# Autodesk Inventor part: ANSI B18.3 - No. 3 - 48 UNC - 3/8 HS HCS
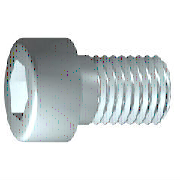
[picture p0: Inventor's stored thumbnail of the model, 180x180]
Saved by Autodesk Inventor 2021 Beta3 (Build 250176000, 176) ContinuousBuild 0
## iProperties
IsCustomPart: 0
Created: 2012-02
Part Number: ANSI B18.3 - No. 3 - 48 UNC - 3/8 HS HCS
Material: Generic
Description: Hexagon Socket Head Cap Screw
Document SubType Name: Modeling
Standard: ANSI B18.3
Designer: John
Standard Revision: 2003
Standards Organization: ANSI
Language: en-US
Size Designation: No. 3 - 48 UNC - 3/8
Categories: <MemberInstance><Categories><Category DisplayName="Fasteners" InternalName="e4da775c-781d-43d5-af7c-5136215cf5a6" Mnemonic="FSTN"><Category DisplayName="Bolts"
Density: 1 g/cm^3
Appearance: Default
Author: John
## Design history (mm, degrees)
sketch "Sketch1"
  geometry: L1 (-0.737, 0)-(9.525, 0); L2 (9.525, 0)-(9.525, 1.257); L3 (9.525, 1.257)-(1.323, 1.257); L4 (1.323, 1.257)-(0, 1.257); L5 (0, 1.257)-(0, 1.257); L6 (0, 1.257)-(0, 2.045); L7 (0, 2.045)-(-2.515, 2.045); L8 (-2.515, 2.045)-(-2.515, 1.144); L9 (-2.515, 1.144)-(-1.397, 1.144); L10 (-1.397, 1.144)-(-0.737, 0); L11 (-4.923, 0)-(11.933, 0) reference; L12 (0, -0.409)-(0, 2.454) reference; L13 (1.323, 1.257)-(0, 1.257)
  constraints: 22 end point, 6 parallel, 2 collinear, 2 perpendicular, 1 horizontal, 1 point on line
  dimensions: "d1" = 8.20197 distance from line of L3.end L2 (= GEL); "d2" = 1.32293 distance of L4.end L3.end (computed from GAL); "d3" = 2.5146 distance between parallel lines of L8 L6 (= KOH); "d4" = 1.1176 distance of L8.end L9.end (= INTI); "d5" = 60 deg angle of L10 L1; "d6" = 2.5146 diameter of L3 L1 (= GD); "d7" = 2.5146 diameter of L5 L1 (= BDM); "d8" = 2.28769 diameter of L9 L1 (= 1.1547 x SW); "d9" = 4.0894 diameter of L7 L1 (= KOD); "d26" = 9.525 distance between parallel lines of L12 L2 (= NLG)
revolve "Body" sketch "Sketch1" stored, may be unused: angle "d10" = 90 deg
sketch "Sketch2"
  geometry: L1 (0, -2.863)-(0, 2.863) reference; L2 (-2.863, 0)-(2.863, 0) reference; L3 (1.144, 0)-(0.572, -0.991); L4 (0.572, -0.991)-(-0.572, -0.991); L5 (-0.572, -0.991)-(-1.144, 0); L6 (-1.144, 0)-(-0.572, 0.991); L7 (-0.572, 0.991)-(0.572, 0.991); L8 (0.572, 0.991)-(1.144, 0); 2 further points
  constraints: 12 end point, 1 coincident, 1 horizontal alignment, 1 point on line, 12 other
extrude "Slot" join sketch "Sketch2" stored distance "d11" = 10; taper "d12" = 0 deg
workplane "Work Plane1"
fillet "Fillet2" dims "d30" = 0.1016 (= R)
body "Solid1"
fillet "Fillet1" dims "d17" = 0.2032 (= RR)
feature "Thread" dims "d13" = 8.20197 (= GEL), "d14" = 0
chamfer "Chamfer1" distance "d15" = 0.31623 (= -0.5 x SPD + 0.5 x GD); stored, may be unused: second distance "d16" = 0.31623 (= GUL), angle "d27" = 45 deg
other parameters: "GD" = 2.5146 [user parameter; used in 2 equation terms], "NLG" = 9.525 [user parameter; used in 1 equation term], "GEL" = 8.20197 [user parameter; used in 2 equation terms], "KOD" = 4.0894 [user parameter; used in 1 equation term], "KOH" = 2.5146 [user parameter; used in 1 equation term], "INTI" = 1.1176 [user parameter; used in 1 equation term], "GAL" = 1.32283 [user parameter; used in 1 equation term], "GUL" = 0.31623 [user parameter; used in 1 equation term], "BDM" = 2.5146 [user parameter; used in 1 equation term], "SW" = 1.9812 [user parameter; used in 2 equation terms], "RR" = 0.2032 [user parameter; used in 1 equation term], "SPD" = 1.88214 [user parameter; used in 2 equation terms], "d19" = 0, "d28" = 0, "d29" = 0, "R" = 0.1016 [user parameter; used in 1 equation term], "PHH" = 0.0762 [user parameter], "GD1" = 1.88214 (= SPD) [user parameter], "THREADDIA" = 2.5146 [user parameter], "FAWI" = 45 deg [user parameter], "PTC" = 0.52917 (computed from TPU) [user parameter], "KOH1" = 2.2606 [user parameter], "NND" = 2.5146 [user parameter], "TOA" = 30 deg [user parameter], "E0" = 2.28829 (= 1.155 x SW) [user parameter]
